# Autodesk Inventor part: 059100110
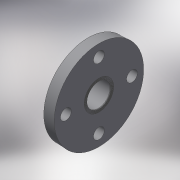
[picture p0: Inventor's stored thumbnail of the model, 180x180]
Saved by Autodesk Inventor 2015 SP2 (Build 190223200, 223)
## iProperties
Created: 2017-10
Part Number: 059100110
Material: Generic
Description: PLASSON FIXED FLANGE-CEM PVC 110
Document SubType Name: Modeling
Designer: KIM
Density: 1 g/cm^3
Appearance: Default
Author: KIM
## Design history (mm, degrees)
derived "059200.ipt"
feature "Solid1::059200.ipt"
tag "TaggingFeature1"
body "Solid1"
other parameters: "d0" = 64, "d3" = 217.8, "d14" = 18, "d16" = 64, "d17" = 0, "d19" = 360 deg, "d21" = 61, "d23" = 104.5, "d24" = 132, "d25" = 1.1, "d26" = 1.1, "d27" = 1.1, "d28" = 1.1, "d29" = 1.1, "d30" = 1.1, "d31" = 1.1, "d32" = 0.44, "d33" = 0, "d34" = 22, "H_" = 64, "S_" = 18, "l_" = 61, "H_1" = 22
